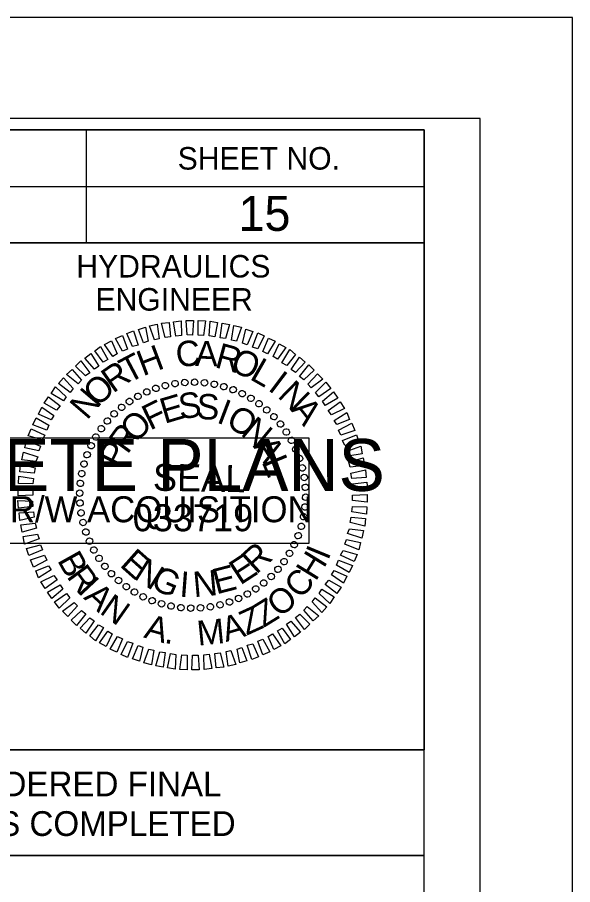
# Model space of a CAD drawing. Extents: x 1779926 to 1781626, y 618464 to 619564.
# Drawn here: x 1781502.7 to 1781626, y 619371.7 to 619564.2 of the extents above; entities that cross this region are included whole.
import ezdxf

# ---------------------------------------------------------------- set-up
doc = ezdxf.new("R2010")
doc.units = 0
for name, color, linetype in [('Old_Level_58', 7, 'Continuous'), ('Sheet Data Field CELL', 7, 'Continuous'), ('Sheet Plot Border Inside CELL', 7, 'Continuous'), ('Sheet Plot Border Outside CELL', 7, 'Continuous'), ('Sheet Professional Seal CELL', 7, 'Continuous'), ('Sheet Profile CELL', 7, 'Continuous'), ('Sheet Profile Grid Major CELL', 7, 'Continuous'), ('Sheet Profile Grid Minor CELL', 7, 'Continuous'), ('Sheet Sticker Exception Certification CELL', 7, 'Continuous'), ('Sheet Sticker Incomplete CELL', 7, 'Continuous')]:
    doc.layers.add(name, color=color, linetype=linetype)

msp = doc.modelspace()

# ---------------------------------------------------------------- linework, layer by layer
at = {"layer": 'Old_Level_58'}
msp.add_lwpolyline([(1781392.96, 619378.14), (1781592.95, 619378.14), (1781592.95, 619314.19), (1781392.96, 619314.19)], close=True, dxfattribs=at)
at = {"layer": 'Sheet Plot Border Inside CELL'}
msp.add_lwpolyline([(1779938.96, 618486.64), (1781605.46, 618486.64), (1781605.46, 619541.74), (1779938.96, 619541.74)], close=True, dxfattribs=at)
at = {"layer": 'Sheet Plot Border Outside CELL'}
msp.add_lwpolyline([(1779925.96, 618464.19), (1781625.96, 618464.19), (1781625.96, 619564.19), (1779925.96, 619564.19)], close=True, dxfattribs=at)
at = {"layer": 'Sheet Professional Seal CELL'}
for p, q in [((1781535.5, 619482.49), (1781535.5, 619482.49)), ((1781537.7, 619482.89), (1781537.7, 619482.89)), ((1781539.85, 619483.19), (1781539.85, 619483.19)), ((1781542.05, 619483.24), (1781542.05, 619483.24)), ((1781544.25, 619483.09), (1781544.25, 619483.09)), ((1781546.4, 619482.74), (1781546.4, 619482.74)), ((1781531.4, 619481.09), (1781531.4, 619481.09)), ((1781533.4, 619481.89), (1781533.4, 619481.89)), ((1781548.5, 619482.29), (1781548.5, 619482.29)), ((1781550.6, 619481.59), (1781550.6, 619481.59)), ((1781552.6, 619480.69), (1781552.6, 619480.69)), ((1781527.55, 619478.94), (1781527.55, 619478.94)), ((1781529.45, 619480.09), (1781529.45, 619480.09)), ((1781554.55, 619479.69), (1781554.55, 619479.69)), ((1781525.8, 619477.69), (1781525.8, 619477.69)), ((1781556.35, 619478.44), (1781556.35, 619478.44)), ((1781558.1, 619477.09), (1781558.1, 619477.09)), ((1781522.65, 619474.64), (1781522.65, 619474.64)), ((1781524.15, 619476.19), (1781524.15, 619476.19)), ((1781559.65, 619475.59), (1781559.65, 619475.59)), ((1781521.3, 619472.89), (1781521.3, 619472.89)), ((1781561.15, 619473.94), (1781561.15, 619473.94)), ((1781520.05, 619471.09), (1781520.05, 619471.09)), ((1781562.4, 619472.19), (1781562.4, 619472.19)), ((1781519.05, 619469.14), (1781519.05, 619469.14)), ((1781563.55, 619470.29), (1781563.55, 619470.29)), ((1781518.15, 619467.14), (1781518.15, 619467.14)), ((1781564.55, 619468.34), (1781564.55, 619468.34)), ((1781517.45, 619465.04), (1781517.45, 619465.04)), ((1781565.35, 619466.34), (1781565.35, 619466.34)), ((1781565.95, 619464.24), (1781565.95, 619464.24)), ((1781517, 619462.94), (1781517, 619462.94)), ((1781566.35, 619462.04), (1781566.35, 619462.04)), ((1781516.65, 619460.79), (1781516.65, 619460.79)), ((1781566.65, 619459.89), (1781566.65, 619459.89)), ((1781516.5, 619458.59), (1781516.5, 619458.59)), ((1781541.6, 619458.14), (1781541.6, 619458.14)), ((1781566.7, 619457.69), (1781566.7, 619457.69)), ((1781516.55, 619456.39), (1781516.55, 619456.39)), ((1781566.55, 619455.49), (1781566.55, 619455.49)), ((1781516.85, 619454.24), (1781516.85, 619454.24)), ((1781517.25, 619452.04), (1781517.25, 619452.04)), ((1781566.2, 619453.34), (1781566.2, 619453.34)), ((1781517.85, 619449.94), (1781517.85, 619449.94)), ((1781565.75, 619451.24), (1781565.75, 619451.24)), ((1781518.65, 619447.94), (1781518.65, 619447.94)), ((1781565.05, 619449.14), (1781565.05, 619449.14)), ((1781519.65, 619445.99), (1781519.65, 619445.99)), ((1781564.15, 619447.14), (1781564.15, 619447.14)), ((1781520.8, 619444.09), (1781520.8, 619444.09)), ((1781563.15, 619445.19), (1781563.15, 619445.19)), ((1781522.05, 619442.34), (1781522.05, 619442.34)), ((1781561.9, 619443.39), (1781561.9, 619443.39)), ((1781523.55, 619440.69), (1781523.55, 619440.69)), ((1781559.05, 619440.09), (1781559.05, 619440.09)), ((1781560.55, 619441.64), (1781560.55, 619441.64)), ((1781525.1, 619439.19), (1781525.1, 619439.19)), ((1781557.4, 619438.59), (1781557.4, 619438.59)), ((1781526.85, 619437.84), (1781526.85, 619437.84)), ((1781528.65, 619436.59), (1781528.65, 619436.59)), ((1781553.75, 619436.19), (1781553.75, 619436.19)), ((1781555.65, 619437.34), (1781555.65, 619437.34)), ((1781530.6, 619435.59), (1781530.6, 619435.59)), ((1781532.6, 619434.69), (1781532.6, 619434.69)), ((1781549.8, 619434.39), (1781549.8, 619434.39)), ((1781551.8, 619435.19), (1781551.8, 619435.19)), ((1781534.7, 619433.99), (1781534.7, 619433.99)), ((1781536.8, 619433.54), (1781536.8, 619433.54)), ((1781538.95, 619433.19), (1781538.95, 619433.19)), ((1781541.15, 619433.04), (1781541.15, 619433.04)), ((1781543.35, 619433.09), (1781543.35, 619433.09)), ((1781545.5, 619433.39), (1781545.5, 619433.39)), ((1781547.7, 619433.79), (1781547.7, 619433.79))]:
    msp.add_line(p, q, dxfattribs=at)
for points in [[(1781533.1, 619492.59), (1781532.05, 619495.74), (1781533.75, 619496.09), (1781534.15, 619492.84)], [(1781535.5, 619493.14), (1781534.7, 619496.34), (1781536.35, 619496.49), (1781536.7, 619493.29)], [(1781537.9, 619493.44), (1781537.35, 619496.64), (1781539.05, 619496.84), (1781539.1, 619493.59)], [(1781540.4, 619493.69), (1781540.15, 619496.94), (1781541.8, 619496.89), (1781541.6, 619493.64)], [(1781542.8, 619493.64), (1781542.8, 619496.89), (1781544.45, 619496.84), (1781544, 619493.59)], [(1781545.3, 619493.49), (1781545.5, 619496.74), (1781547.15, 619496.44), (1781546.5, 619493.29)], [(1781547.7, 619493.09), (1781548.15, 619496.29), (1781549.8, 619496.04), (1781548.9, 619492.94)], [(1781528.25, 619491.14), (1781526.95, 619494.04), (1781528.45, 619494.64), (1781529.5, 619491.44)], [(1781530.7, 619491.94), (1781529.55, 619494.94), (1781531.1, 619495.39), (1781531.75, 619492.29)], [(1781550.25, 619492.54), (1781550.75, 619495.79), (1781552.45, 619495.39), (1781551.3, 619492.29)], [(1781552.65, 619491.89), (1781553.4, 619494.99), (1781554.95, 619494.49), (1781553.7, 619491.54)], [(1781554.9, 619490.99), (1781556.05, 619494.14), (1781557.45, 619493.54), (1781556.05, 619490.64)], [(1781523.9, 619488.89), (1781522.05, 619491.59), (1781523.6, 619492.39), (1781524.85, 619489.49)], [(1781526.05, 619490.09), (1781524.45, 619492.89), (1781526, 619493.59), (1781527.15, 619490.54)], [(1781557.15, 619490.04), (1781558.4, 619492.99), (1781559.95, 619492.29), (1781558.25, 619489.49)], [(1781521.7, 619487.64), (1781519.85, 619490.19), (1781521.15, 619491.14), (1781522.8, 619488.24)], [(1781559.45, 619488.89), (1781560.8, 619491.74), (1781562.3, 619490.89), (1781560.4, 619488.29)], [(1781561.4, 619487.54), (1781563.15, 619490.44), (1781564.45, 619489.39), (1781562.5, 619486.94)], [(1781519.8, 619486.14), (1781517.65, 619488.54), (1781519, 619489.59), (1781520.75, 619486.79)], [(1781563.45, 619486.04), (1781565.3, 619488.79), (1781566.6, 619487.69), (1781564.4, 619485.34)], [(1781517.8, 619484.59), (1781515.6, 619486.79), (1781516.8, 619487.99), (1781518.75, 619485.29)], [(1781565.35, 619484.49), (1781567.4, 619487.09), (1781568.6, 619485.89), (1781566.3, 619483.74)], [(1781516.15, 619482.84), (1781513.6, 619484.89), (1781514.85, 619486.04), (1781516.95, 619483.64)], [(1781567.15, 619482.74), (1781569.3, 619485.09), (1781570.5, 619483.89), (1781567.9, 619481.94)], [(1781514.4, 619480.94), (1781511.8, 619482.89), (1781512.9, 619484.19), (1781515.1, 619481.84)], [(1781568.9, 619480.94), (1781571.2, 619483.19), (1781572.25, 619481.84), (1781569.6, 619479.94)], [(1781512.9, 619479.04), (1781510.2, 619480.74), (1781511.15, 619482.19), (1781513.55, 619479.99)], [(1781570.4, 619478.99), (1781572.85, 619481.09), (1781573.8, 619479.64), (1781571, 619478.04)], [(1781511.4, 619477.04), (1781508.6, 619478.54), (1781509.6, 619479.94), (1781512.2, 619477.94)], [(1781571.7, 619476.94), (1781574.35, 619478.84), (1781575.3, 619477.34), (1781572.4, 619475.94)], [(1781510.2, 619474.89), (1781507.35, 619476.14), (1781508.1, 619477.69), (1781510.8, 619475.84)], [(1781509.2, 619472.59), (1781506.1, 619473.74), (1781506.85, 619475.29), (1781509.7, 619473.69)], [(1781573, 619474.74), (1781575.8, 619476.49), (1781576.45, 619474.94), (1781573.6, 619473.79)], [(1781508.2, 619470.39), (1781505.1, 619471.29), (1781505.75, 619472.84), (1781508.75, 619471.44)], [(1781574, 619472.59), (1781576.95, 619474.09), (1781577.6, 619472.49), (1781574.5, 619471.49)], [(1781574.9, 619470.24), (1781577.95, 619471.54), (1781578.5, 619469.99), (1781575.4, 619469.19)], [(1781507.45, 619467.99), (1781504.35, 619468.64), (1781504.7, 619470.29), (1781507.85, 619469.04)], [(1781575.7, 619467.84), (1781578.9, 619468.99), (1781579.2, 619467.34), (1781576.05, 619466.79)], [(1781506.8, 619465.59), (1781503.7, 619465.99), (1781504.05, 619467.69), (1781507.2, 619466.64)], [(1781506.4, 619463.04), (1781503.2, 619463.34), (1781503.4, 619465.04), (1781506.65, 619464.24)], [(1781576.3, 619465.44), (1781579.45, 619466.39), (1781579.75, 619464.69), (1781576.6, 619464.39)], [(1781576.75, 619463.04), (1781580, 619463.74), (1781580.15, 619462.04), (1781576.95, 619461.84)], [(1781506.15, 619460.64), (1781502.9, 619460.74), (1781503, 619462.39), (1781506.25, 619461.84)], [(1781506.1, 619458.14), (1781502.85, 619457.99), (1781502.85, 619459.69), (1781506.1, 619459.34)], [(1781577.05, 619460.64), (1781580.3, 619461.04), (1781580.4, 619459.34), (1781577.15, 619459.44)], [(1781577.1, 619458.14), (1781580.35, 619458.29), (1781580.35, 619456.59), (1781577.1, 619456.94)], [(1781506.15, 619455.64), (1781502.9, 619455.24), (1781502.8, 619456.94), (1781506.05, 619456.84)], [(1781577.05, 619455.64), (1781580.3, 619455.54), (1781580.2, 619453.89), (1781576.95, 619454.44)], [(1781506.45, 619453.24), (1781503.2, 619452.54), (1781503.05, 619454.24), (1781506.25, 619454.44)], [(1781506.9, 619450.84), (1781503.75, 619449.89), (1781503.45, 619451.59), (1781506.6, 619451.89)], [(1781576.8, 619453.24), (1781580, 619452.94), (1781579.8, 619451.24), (1781576.55, 619452.04)], [(1781576.4, 619450.69), (1781579.5, 619450.29), (1781579.15, 619448.59), (1781576, 619449.64)], [(1781507.5, 619448.44), (1781504.3, 619447.29), (1781504, 619448.94), (1781507.15, 619449.49)], [(1781575.75, 619448.29), (1781578.85, 619447.64), (1781578.5, 619445.99), (1781575.35, 619447.24)], [(1781508.3, 619446.04), (1781505.25, 619444.74), (1781504.7, 619446.29), (1781507.8, 619447.09)], [(1781575, 619445.89), (1781578.1, 619444.99), (1781577.45, 619443.44), (1781574.45, 619444.84)], [(1781509.2, 619443.69), (1781506.25, 619442.19), (1781505.6, 619443.79), (1781508.7, 619444.79)], [(1781510.2, 619441.54), (1781507.4, 619439.79), (1781506.75, 619441.34), (1781509.6, 619442.49)], [(1781574, 619443.69), (1781577.1, 619442.54), (1781576.35, 619440.99), (1781573.5, 619442.59)], [(1781511.5, 619439.34), (1781508.85, 619437.44), (1781507.9, 619438.94), (1781510.8, 619440.34)], [(1781573, 619441.39), (1781575.85, 619440.14), (1781575.1, 619438.59), (1781572.4, 619440.44)], [(1781512.8, 619437.29), (1781510.35, 619435.19), (1781509.4, 619436.64), (1781512.2, 619438.24)], [(1781571.8, 619439.24), (1781574.6, 619437.74), (1781573.6, 619436.34), (1781571, 619438.34)], [(1781514.3, 619435.34), (1781512, 619433.09), (1781510.95, 619434.44), (1781513.6, 619436.34)], [(1781570.3, 619437.24), (1781573, 619435.54), (1781572.05, 619434.09), (1781569.65, 619436.29)], [(1781516.05, 619433.54), (1781513.9, 619431.19), (1781512.7, 619432.39), (1781515.3, 619434.34)], [(1781568.8, 619435.34), (1781571.4, 619433.39), (1781570.3, 619432.09), (1781568.1, 619434.44)], [(1781517.85, 619431.79), (1781515.8, 619429.19), (1781514.6, 619430.39), (1781516.9, 619432.54)], [(1781567.05, 619433.44), (1781569.6, 619431.39), (1781568.35, 619430.24), (1781566.25, 619432.64)], [(1781519.75, 619430.24), (1781517.9, 619427.49), (1781516.6, 619428.59), (1781518.8, 619430.94)], [(1781565.4, 619431.69), (1781567.6, 619429.49), (1781566.4, 619428.29), (1781564.45, 619430.99)], [(1781521.8, 619428.74), (1781520.05, 619425.84), (1781518.75, 619426.89), (1781520.7, 619429.34)], [(1781561.5, 619428.64), (1781563.35, 619426.09), (1781562.05, 619425.14), (1781560.4, 619428.04)], [(1781563.4, 619430.14), (1781565.55, 619427.74), (1781564.2, 619426.69), (1781562.45, 619429.49)], [(1781523.75, 619427.39), (1781522.4, 619424.54), (1781520.9, 619425.39), (1781522.8, 619427.99)], [(1781526.05, 619426.24), (1781524.8, 619423.29), (1781523.25, 619423.99), (1781524.95, 619426.79)], [(1781559.3, 619427.39), (1781561.15, 619424.69), (1781559.6, 619423.89), (1781558.35, 619426.79)], [(1781528.3, 619425.29), (1781527.15, 619422.14), (1781525.75, 619422.74), (1781527.15, 619425.64)], [(1781530.55, 619424.39), (1781529.8, 619421.29), (1781528.25, 619421.79), (1781529.5, 619424.74)], [(1781554.95, 619425.14), (1781556.25, 619422.24), (1781554.75, 619421.64), (1781553.7, 619424.84)], [(1781557.15, 619426.19), (1781558.75, 619423.39), (1781557.2, 619422.69), (1781556.05, 619425.74)], [(1781532.95, 619423.74), (1781532.45, 619420.49), (1781530.75, 619420.89), (1781531.9, 619423.99)], [(1781535.5, 619423.19), (1781535.05, 619419.99), (1781533.4, 619420.24), (1781534.3, 619423.34)], [(1781537.9, 619422.79), (1781537.7, 619419.54), (1781536.05, 619419.84), (1781536.7, 619422.99)], [(1781540.4, 619422.64), (1781540.4, 619419.39), (1781538.75, 619419.44), (1781539.2, 619422.69)], [(1781545.3, 619422.84), (1781545.85, 619419.64), (1781544.15, 619419.44), (1781544.1, 619422.69)], [(1781547.7, 619423.14), (1781548.5, 619419.94), (1781546.85, 619419.79), (1781546.5, 619422.99)], [(1781550.1, 619423.69), (1781551.15, 619420.54), (1781549.45, 619420.19), (1781549.05, 619423.44)], [(1781552.5, 619424.34), (1781553.65, 619421.34), (1781552.1, 619420.89), (1781551.45, 619423.99)], [(1781542.8, 619422.59), (1781543.05, 619419.34), (1781541.4, 619419.39), (1781541.6, 619422.64)]]:
    msp.add_lwpolyline(points, close=True, dxfattribs=at)
for centre, major_axis in [((1781533.43, 619481.85), (-0.234, 0.681)), ((1781535.53, 619482.47), (-0.174, 0.699)), ((1781537.68, 619482.91), (-0.113, 0.711)), ((1781539.85, 619483.15), (-0.05, 0.718)), ((1781542.04, 619483.21), (0.013, 0.72)), ((1781544.22, 619483.08), (0.075, 0.716)), ((1781546.39, 619482.75), (0.137, 0.707)), ((1781548.51, 619482.24), (0.198, 0.692)), ((1781550.59, 619481.55), (0.258, 0.672)), ((1781529.44, 619480.07), (-0.349, 0.63)), ((1781531.4, 619481.05), (-0.293, 0.658)), ((1781552.59, 619480.68), (0.316, 0.647)), ((1781554.52, 619479.63), (0.371, 0.617)), ((1781527.58, 619478.93), (-0.403, 0.597)), ((1781556.34, 619478.43), (0.423, 0.582)), ((1781524.18, 619476.18), (-0.5, 0.518)), ((1781525.82, 619477.63), (-0.453, 0.56)), ((1781558.05, 619477.06), (0.472, 0.543)), ((1781522.67, 619474.59), (-0.543, 0.472)), ((1781559.64, 619475.56), (0.518, 0.5)), ((1781561.09, 619473.92), (0.56, 0.453)), ((1781521.31, 619472.88), (-0.582, 0.423)), ((1781562.39, 619472.16), (0.597, 0.403)), ((1781520.1, 619471.05), (-0.617, 0.371)), ((1781563.54, 619470.29), (0.63, 0.349)), ((1781519.06, 619469.13), (-0.647, 0.316)), ((1781564.51, 619468.34), (0.658, 0.293)), ((1781518.19, 619467.12), (-0.672, 0.258)), ((1781565.31, 619466.3), (0.681, 0.234)), ((1781517.49, 619465.05), (-0.692, 0.198)), ((1781516.98, 619462.92), (-0.707, 0.137)), ((1781565.93, 619464.2), (0.699, 0.174)), ((1781516.66, 619460.76), (-0.716, 0.075)), ((1781566.37, 619462.06), (0.711, 0.113)), ((1781516.52, 619458.57), (-0.72, 0.013)), ((1781566.62, 619459.88), (0.718, 0.05)), ((1781566.68, 619457.7), (0.72, -0.013)), ((1781516.58, 619456.39), (-0.718, -0.05)), ((1781566.54, 619455.51), (0.716, -0.075)), ((1781516.83, 619454.21), (-0.711, -0.113)), ((1781566.22, 619453.35), (0.707, -0.137)), ((1781517.26, 619452.07), (-0.699, -0.174)), ((1781565.71, 619451.22), (0.692, -0.198)), ((1781517.89, 619449.97), (-0.681, -0.234)), ((1781565.01, 619449.15), (0.672, -0.258)), ((1781518.69, 619447.93), (-0.658, -0.293)), ((1781564.14, 619447.14), (0.647, -0.316)), ((1781519.66, 619445.98), (-0.63, -0.349)), ((1781563.1, 619445.22), (0.617, -0.371)), ((1781520.81, 619444.11), (-0.597, -0.403)), ((1781561.89, 619443.39), (0.582, -0.423)), ((1781522.11, 619442.35), (-0.56, -0.453)), ((1781560.53, 619441.68), (0.543, -0.472)), ((1781523.56, 619440.71), (-0.518, -0.5)), ((1781525.15, 619439.21), (-0.472, -0.543)), ((1781559.02, 619440.09), (0.5, -0.518)), ((1781526.86, 619437.84), (-0.423, -0.582)), ((1781555.62, 619437.34), (0.403, -0.597)), ((1781557.38, 619438.64), (0.453, -0.56)), ((1781528.68, 619436.64), (-0.371, -0.617)), ((1781530.61, 619435.59), (-0.316, -0.647)), ((1781553.76, 619436.2), (0.349, -0.63)), ((1781532.61, 619434.72), (-0.258, -0.672)), ((1781534.69, 619434.03), (-0.198, -0.692)), ((1781536.81, 619433.52), (-0.137, -0.707)), ((1781547.67, 619433.8), (0.174, -0.699)), ((1781549.77, 619434.42), (0.234, -0.681)), ((1781551.8, 619435.22), (0.293, -0.658)), ((1781538.98, 619433.19), (-0.075, -0.716)), ((1781541.16, 619433.06), (-0.013, -0.72)), ((1781543.35, 619433.12), (0.05, -0.718)), ((1781545.52, 619433.36), (0.113, -0.711))]:
    msp.add_ellipse(centre, major_axis=major_axis, ratio=0.999708, dxfattribs=at)
at = {"layer": 'Sheet Profile CELL'}
for p, q in [((1781517.96, 619539.14), (1781517.96, 619514.14)), ((1781392.91, 619526.64), (1781592.96, 619526.64))]:
    msp.add_line(p, q, dxfattribs=at)
for points in [[(1781592.96, 619539.19), (1780092.96, 619539.19), (1780092.96, 618489.19), (1781592.96, 618489.19)], [(1781392.91, 619539.19), (1781592.96, 619539.19), (1781592.96, 619514.14), (1781392.91, 619514.14)], [(1781492.96, 619514.14), (1781592.96, 619514.14), (1781592.96, 619401.64), (1781492.96, 619401.64)]]:
    msp.add_lwpolyline(points, close=True, dxfattribs=at)
at = {"layer": 'Sheet Profile Grid Major CELL'}
msp.add_lwpolyline([(1781542.96, 619314.19), (1781542.96, 619039.19), (1781592.96, 619039.19), (1781592.96, 619389.19)], dxfattribs=at)
at = {"layer": 'Sheet Sticker Exception Certification CELL'}
for p, q in [((1781392.91, 619401.64), (1781592.95, 619401.64)), ((1781392.91, 619401.64), (1781592.95, 619401.64)), ((1781592.95, 619401.63), (1781592.95, 619378.13)), ((1781592.95, 619401.63), (1781592.95, 619378.13)), ((1781592.95, 619378.14), (1781392.91, 619378.14)), ((1781592.95, 619378.14), (1781392.91, 619378.14))]:
    msp.add_line(p, q, dxfattribs=at)
at = {"layer": 'Sheet Sticker Incomplete CELL'}
msp.add_lwpolyline([(1781420.37, 619447.38), (1781420.37, 619470.88), (1781567.37, 619470.88), (1781567.37, 619447.38)], close=True, dxfattribs=at)

# ---------------------------------------------------------------- texts
at = {"layer": 'Sheet Data Field CELL'}
msp.add_text('15', height=7.75, dxfattribs=at).set_placement((1781551.78, 619516.8))
at = {"layer": 'Sheet Professional Seal CELL'}
for s, height, rotation, p in [('C', 5.64, 6.2199, (1781538.15, 619486.49)), ('A', 5.64, 359.0203, (1781542.1, 619486.79)), ('H', 5.64, 20.6195, (1781530.55, 619484.49)), ('R', 5.64, 344.6211, (1781546.3, 619486.59)), ('O', 5.64, 337.4212, (1781549.65, 619485.84)), ('T', 5.64, 27.8198, (1781527.3, 619482.84)), ('L', 5.64, 330.2209, (1781554.05, 619483.99)), ('R', 5.64, 35.0205, (1781523.9, 619480.64)), ('O', 5.64, 42.2217, (1781520.45, 619477.54)), ('I', 5.64, 323.0201, (1781558.1, 619481.59)), ('N', 5.64, 315.8189, (1781560.25, 619480.04)), ('N', 5.64, 49.4235, (1781518.15, 619474.64)), ('E', 5.64, 16.6111, (1781535.35, 619473.94)), ('S', 5.64, 7.2556, (1781538.8, 619474.99)), ('S', 5.64, 357.9004, (1781542.4, 619475.04)), ('F', 5.64, 25.967, (1781532.15, 619472.44)), ('I', 5.64, 339.1896, (1781546.7, 619474.34)), ('A', 5.64, 308.6172, (1781563.2, 619477.09)), ('O', 5.64, 329.8335, (1781548.7, 619473.64)), ('O', 5.64, 44.6812, (1781528.85, 619469.49)), ('N', 5.64, 320.4766, (1781552.05, 619471.64)), ('R', 5.64, 54.0397, (1781527.1, 619467.04)), ('P', 5.64, 63.3989, (1781525.5, 619463.84)), ('A', 5.64, 301.7603, (1781554.9, 619469.04)), ('L', 5.64, 292.4008, (1781556.85, 619465.59)), ('SEAL', 5.998, 359, (1781532.75, 619459.14)), ('E', 5.64, 318.2769, (1781525.2, 619442.49)), ('R', 5.64, 42.4814, (1781555.7, 619440.39)), ('N', 5.64, 327.634, (1781528.2, 619439.79)), ('E', 5.64, 33.1241, (1781552.15, 619438.04)), ('G', 5.64, 336.9902, (1781532, 619437.54)), ('E', 5.64, 14.4118, (1781546.85, 619436.09)), ('I', 5.64, 355.7012, (1781538.55, 619435.64)), ('N', 5.64, 5.0564, (1781541.9, 619435.49))]:
    msp.add_text(s, height=height, rotation=rotation, dxfattribs=at).set_placement(p)
at = {"layer": 'Sheet Profile CELL'}
for s, p in [('SHEET NO.', (1781538.27, 619530.4)), ('HYDRAULICS', (1781515.77, 619506.45)), ('ENGINEER', (1781520.02, 619499.1))]:
    msp.add_text(s, height=5, dxfattribs=at).set_placement(p)
at = {"layer": 'Sheet Profile Grid Minor CELL'}
msp.add_text('033719', height=5.998, dxfattribs=at).set_placement((1781528.28, 619450.13))
for s, rotation, p in [('B', 299.1529, (1781511.45, 619443.69)), ('H', 58.3478, (1781568.91, 619438.86)), ('I', 67.5926, (1781571.65, 619443.5)), ('R', 306.2797, (1781513.48, 619440.07)), ('I', 313.2061, (1781515.86, 619436.81)), ('C', 49.4751, (1781565.61, 619434.88)), ('A', 316.7266, (1781517.22, 619435.27)), ('N', 324.9124, (1781520.72, 619432.03)), ('O', 38.7706, (1781560.87, 619430.82)), ('Z', 31.6438, (1781557.34, 619428.64)), ('Z', 24.517, (1781553.56, 619426.92)), ('A', 344.2893, (1781530.57, 619426.58)), ('M', 5.6554, (1781542.82, 619424.73)), ('A', 16.3312, (1781548.99, 619425.53)), ('.', 352.4751, (1781535.17, 619425.33))]:
    msp.add_text(s, height=5.5, rotation=rotation, dxfattribs=at).set_placement(p)
at = {"layer": 'Sheet Sticker Exception Certification CELL'}
for s, p in [('DOCUMENT NOT CONSIDERED FINAL', (1781413.98, 619391.3)), ('DOCUMENT NOT CONSIDERED FINAL', (1781413.98, 619391.3)), ('UNLESS ALL SIGNATURES COMPLETED', (1781408.91, 619382.5)), ('UNLESS ALL SIGNATURES COMPLETED', (1781408.91, 619382.5))]:
    msp.add_text(s, height=5.5, dxfattribs=at).set_placement(p)
at = {"layer": 'Sheet Sticker Incomplete CELL'}
for s, height, p in [('INCOMPLETE PLANS', 11.52, (1781429.32, 619459.08)), ('DO NOT USE FOR R/W ACQUISITION', 5.76, (1781432.57, 619452.13))]:
    msp.add_text(s, height=height, dxfattribs=at).set_placement(p)

doc.saveas('drawing.dxf')
